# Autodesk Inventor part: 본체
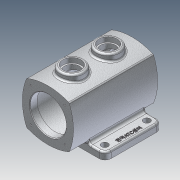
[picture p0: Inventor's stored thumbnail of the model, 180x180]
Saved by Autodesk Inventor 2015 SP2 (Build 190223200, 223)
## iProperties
Created: 2013-02
Part Number: 본체
Document SubType Name: Modeling
Designer: 한국산업디자인학원[gmhk.co.kr]
Density: 1 g/cm^3
Material: 일반
Appearance: _시험_알루미늄 표면거칠기
Mass: 447.452 g
Surface Area: 1019.32 cm^2
Volume: 447.452 cm^3
Author: 한국산업디자인학원[gmhk.co.kr]
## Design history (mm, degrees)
sketch "스케치1"
  geometry: L1 (-65, 55)-(65, 55); L2 (65, 55)-(65, -40); L3 (65, -40)-(-65, -40); L4 (-65, -40)-(-65, 55); 2 further points
  constraints: 8 end point, 2 parallel, 1 horizontal, 1 midpoint, 1 perpendicular, 1 vertical alignment
  dimensions: "d0" = 130 distance of L2.end L3.end; "d1" = 95 distance of L1.end L2.end; "d47" = 40 distance from line of L3 point (0, 0)
extrude "돌출1" new body sketch "스케치1" distance "d2" = 12; taper "d3" = 0 deg
sketch "스케치2"
  geometry: L1 (-35.355, 85.355)-(35.355, 85.355); L2 (35.355, 85.355)-(35.355, 14.645); L3 (35.355, 14.645)-(-35.355, 14.645); L4 (-35.355, 14.645)-(-35.355, 85.355); L5 (35.355, 85.355)-(-35.355, 14.645); L6 (65, 0)-(-65, 0) reference; A1 r 91.05 centre (0, 1.45) between (35.355, 85.355) and (-35.355, 85.355); A2 r 91.05 centre (-48.55, 50) between (35.355, 14.645) and (35.355, 85.355); A3 r 91.05 centre (0, 98.55) between (-35.355, 14.645) and (35.355, 14.645); A4 r 91.05 centre (48.55, 50) between (-35.355, 85.355) and (-35.355, 14.645); 3 further points
  constraints: 10 end point, 8 point on circle, 4 centre point, 3 equal radius, 2 midpoint, 2 parallel, 2 perpendicular, 1 horizontal, 1 vertical alignment
  dimensions: "d4" = 50 distance from line of point (0, 50) L6; "d5" = 50 distance of L1.start point (0, 50); "d6" = 85 dimension on A2 A4
extrude "돌출2" join sketch "스케치2" stored distance "d7" = 140; taper "d8" = 0 deg
sketch "스케치3"
  geometry: L1 (28.27, 12)-(65, 12) reference; L2 (-65, 12)-(-28.27, 12) reference; A1 r 91.05 centre (0, 98.55) between (-35.355, 14.645) and (35.355, 14.645) reference; A2 r 91.05 centre (48.55, 50) between (-35.355, 85.355) and (-35.355, 14.645) reference; A3 r 91.05 centre (-48.55, 50) between (35.355, 14.645) and (35.355, 85.355) reference; A4 r 5 centre (-41.653, 17) between (-41.653, 12) and (-36.957, 18.718); A5 r 5 centre (41.653, 17) between (36.957, 18.718) and (41.653, 12); 1 further point
  constraints: 6 point on circle, 4 tangent, 2 centre point, 2 point on line, 1 equal radius
  dimensions: "d9" = 5 radius of A5
extrude "돌출3" join sketch "스케치3" stored distance "d10" = 120; taper "d11" = 0 deg
fillet "모깎기1" dims "d12" = 3
fillet "모깎기2" dims "d13" = 10
fillet "모깎기3" dims "d14" = 3
sketch "스케치4"
  geometry: L1 (-70, 84.185)-(-70, 85.839) reference; L2 (-70, 15.815)-(-70, 84.185) reference; L3 (-70, 14.161)-(-70, 15.815) reference; L4 (-70, 14.161)-(-70, 14.161) reference; L5 (-70, 15.815)-(-70, 14.161) reference; L6 (-70, 84.185)-(-70, 15.815) reference; L7 (-70, 85.839)-(-70, 84.185) reference; L8 (-70, 85.839)-(-70, 85.839) reference; L9 (70, 15.815)-(70, 14.161) reference; L10 (70, 84.185)-(70, 15.815) reference; L11 (70, 85.839)-(70, 84.185) reference; L12 (70, 85.839)-(70, 85.839) reference; L13 (70, 84.185)-(70, 85.839) reference; L14 (70, 15.815)-(70, 84.185) reference; L15 (70, 14.161)-(70, 15.815) reference; L16 (70, 14.161)-(70, 14.161) reference; L17 (-70, 50)-(70, 50); L18 (-70, 80)-(-58, 80); L19 (-58, 80)-(-58, 87.5); L20 (-58, 87.5)-(58, 87.5); L21 (58, 87.5)-(58, 80); L22 (58, 80)-(70, 80); 1 further point
  constraints: 12 end point, 2 collinear, 2 midpoint, 2 parallel, 2 perpendicular, 2 point on line
  dimensions: "d15" = 60 diameter of L18 L17; "d16" = 75 diameter of L20 L17; "d17" = 12 distance of L18.start L18.end; "d18" = 12 distance of L21.end L22.end
revolve "회전1" sketch "스케치4" stored, may be unused: angle "d19" = 90 deg
fillet "모깎기4" dims "d20" = 3
node "작업 평면2"
  node "작업 평면1"
sketch "스케치5"
  geometry: C1 r 20 at (0, 30); C2 r 20 at (0, -30); 1 further point
  constraints: 2 centre point, 2 vertical alignment
  dimensions: "d22" = 40 diameter of C1; "d23" = 40 diameter of C2; "d24" = 60 distance of C2.centre C1.centre; "d25" = 30 distance of point (0, 0) C1.centre (= 0.5 x d24)
extrude "돌출4" join sketch "스케치5" stored distance "d26" = 120; taper "d27" = 0 deg
fillet "모깎기5" dims "d28" = 3
hole "구멍1" diameter "d31" = 25; stored, may be unused: countersink angle "d35" = 90 deg, drill point angle "d37" = 118 deg; dims "d29" = 10, "d30" = 10, "d32" = 6, "d33" = 30, "d34" = 8, "d36" = 8
hole "구멍2" diameter "d40" = 25; stored, may be unused: countersink angle "d44" = 90 deg, drill point angle "d46" = 118 deg; dims "d38" = 10, "d39" = 10, "d41" = 6, "d42" = 30, "d43" = 8, "d45" = 8
sketch "스케치6"
  geometry: L1 (65, -30)-(65, 45) reference; 4 further points
  constraints: 1 midpoint, 1 vertical alignment
  dimensions: "d48" = 13 distance from line of point (52, 42.5) L1; "d49" = 70 distance of point (52, -27.5) point (52, 42.5); "d50" = 35 vertical distance of point (65, 7.5) point (52, 42.5) (= 0.5 x d49)
hole "구멍3" sketch "스케치6" at (52, -27.5), (52, 42.5) diameter "d51" = 11; stored, may be unused: countersink angle "d55" = 90 deg, drill point angle "d57" = 118 deg; dims "d52" = 6, "d53" = 30, "d54" = 8, "d56" = 8
sketch "스케치8"
  geometry: L1 (65, -30)-(65, 45) reference; 3 further points
  constraints: 1 horizontal alignment, 1 midpoint, 1 other
  dimensions: "d60" = 8 distance from line of point (57, 7.5) L1
feature "엠보싱2" sketch "스케치8" dims "d0" = 130, "d1" = 95, "d47" = 40, "d61" = 1, "d62" = 0
chamfer "모따기1" distance "d63" = 1; stored, may be unused: second distance "d64" = 2, angle "d65" = 45 deg
sketch "스케치9" dims "d9" = 5
  geometry: L1 (0, 81)-(0, 50); L2 (0, 50)-(28.284, 78.284); 1 further point
  constraints: 4 end point, 1 vertical, 1 vertical alignment, 1 other
  dimensions: "d66" = 45 deg angle of L2 L1; "d67" = 40 distance of L2.end L1.end
hole "구멍4" sketch "스케치9" at (28.284, 78.284) diameter "d68" = 3.242; stored, may be unused: countersink angle "d72" = 90 deg, drill point angle "d74" = 118 deg; dims "d69" = 8, "d70" = 30, "d71" = 8, "d73" = 10
node "솔리드1"
mirror "대칭1"
pattern_circular "원형 패턴1" dims angle "d76" = 360 deg
mirror "대칭2"
node "투영된 루프1"
node "투영된 루프2"
